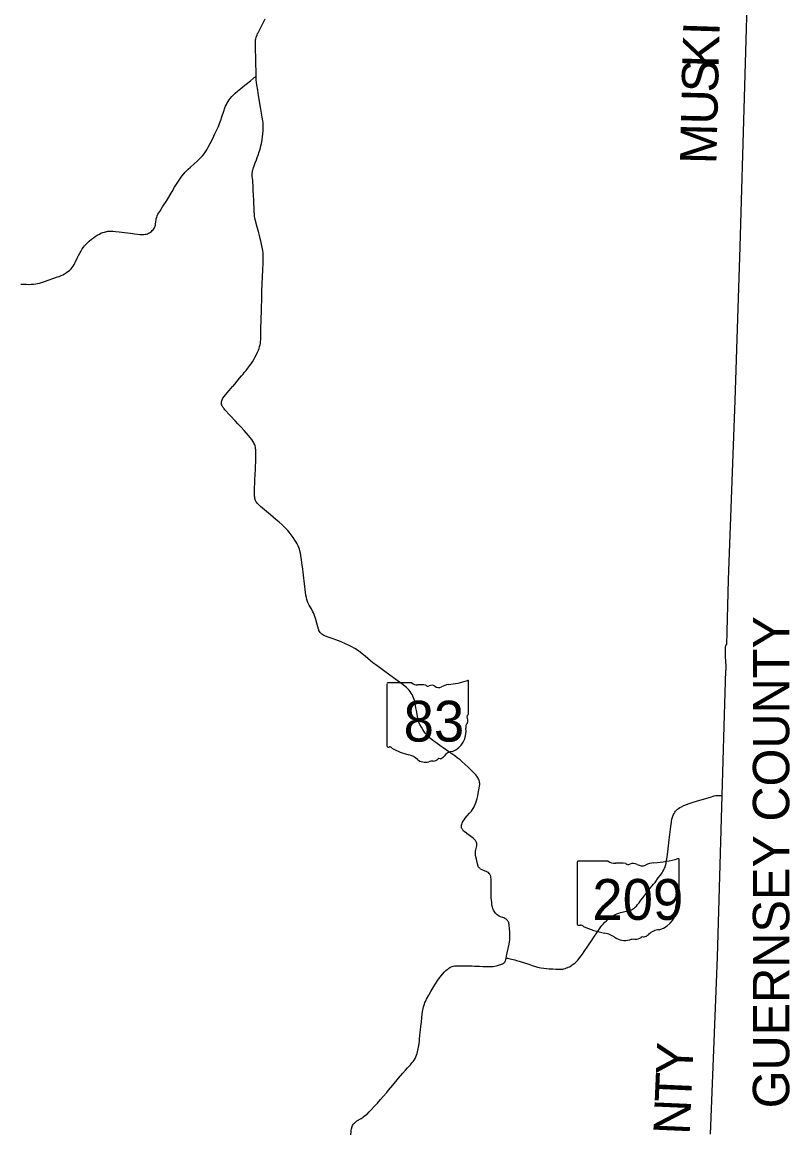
# Model space of a CAD drawing. Extents: x 2015843 to 2287843, y 623733 to 799733.
# Drawn here: x 2182200 to 2203288, y 737859 to 768366 of the extents above; entities that cross this region are included whole.
import ezdxf

# ---------------------------------------------------------------- set-up
doc = ezdxf.new("R2010")
doc.units = 0
for name, color, linetype in [('GM_X_County', 7, 'Continuous'), ('GM_X_County_Text', 7, 'Continuous'), ('GM_X_State_Location', 7, 'Continuous'), ('GM_X_State_Route', 7, 'Continuous'), ('GM_X_State_Shield', 7, 'Continuous')]:
    doc.layers.add(name, color=color, linetype=linetype)

msp = doc.modelspace()

# ---------------------------------------------------------------- linework, layer by layer
at = {"layer": 'GM_X_County'}
msp.add_lwpolyline([(2202153, 770412), (2201913, 762197), (2201774, 757977), (2201599, 753053), (2201548, 751275), (2201535, 751259), (2201527, 751247), (2201523, 751239), (2201518, 751226), (2201514, 751209), (2201511, 751194), (2201509, 751176), (2201509, 751156), (2201510, 751119), (2201511, 751074), (2201513, 751019), (2201516, 750940), (2201524, 750806), (2201531, 750688), (2201534, 750628), (2201532, 750592), (2201531, 750578), (2201529, 750569), (2201526, 750557), (2201479, 749033), (2201419, 747129), (2201296, 742683), (2201102, 737817)], dxfattribs=at)
at = {"layer": 'GM_X_State_Route'}
for points in [[(2188669, 768052), (2188682, 768076), (2188793, 768292), (2188847, 768408), (2188873, 768462)], [(2188609, 767690), (2188608, 767749), (2188609, 767831), (2188612, 767879), (2188617, 767911), (2188624, 767942), (2188627, 767954)], [(2188627, 767954), (2188634, 767973), (2188652, 768018), (2188669, 768052)], [(2188628, 766868), (2188628, 766930), (2188609, 767690)], [(2182163, 761171), (2182313, 761166), (2182379, 761165), (2182444, 761167), (2182510, 761171), (2182575, 761179), (2182623, 761187), (2182671, 761198), (2182734, 761215), (2182811, 761241), (2183166, 761368), (2183212, 761385), (2183273, 761410), (2183317, 761430), (2183360, 761454), (2183416, 761488), (2183457, 761515), (2183495, 761545), (2183519, 761567), (2183541, 761591), (2183572, 761628), (2183600, 761668), (2183625, 761710), (2183645, 761750), (2183655, 761769), (2183709, 761886), (2183748, 761960), (2183779, 762018), (2183819, 762088), (2183852, 762143), (2183882, 762185), (2183911, 762224), (2183945, 762263), (2183990, 762310), (2184039, 762355), (2184102, 762405), (2184156, 762446), (2184207, 762480), (2184262, 762515), (2184320, 762546), (2184364, 762567), (2184411, 762586), (2184457, 762603), (2184489, 762612), (2184521, 762619), (2184555, 762624), (2184591, 762626), (2184636, 762627), (2184692, 762625), (2184767, 762619), (2184865, 762607), (2185010, 762590), (2185092, 762580), (2185173, 762568), (2185286, 762552), (2185366, 762542), (2185431, 762535), (2185480, 762533), (2185513, 762533), (2185545, 762535), (2185577, 762540), (2185608, 762547), (2185639, 762557), (2185669, 762569), (2185697, 762584), (2185725, 762601), (2185750, 762620), (2185775, 762642), (2185795, 762663), (2185816, 762690), (2185833, 762718), (2185846, 762744), (2185853, 762762), (2185861, 762793), (2185866, 762824), (2185872, 762886), (2185880, 762937), (2185885, 762969), (2185897, 763012), (2185911, 763048), (2185930, 763089), (2185951, 763126), (2185978, 763171), (2186056, 763292), (2186169, 763471), (2186320, 763720), (2186387, 763833), (2186455, 763945), (2186508, 764029), (2186545, 764083), (2186585, 764135), (2186638, 764198), (2186681, 764245), (2186704, 764271), (2186762, 764330), (2186822, 764387), (2186920, 764474), (2187006, 764549), (2187066, 764605), (2187112, 764652), (2187156, 764700), (2187197, 764751), (2187235, 764804), (2187270, 764859), (2187311, 764930), (2187365, 765032), (2187416, 765134), (2187465, 765238), (2187493, 765297), (2187558, 765430), (2187591, 765505), (2187622, 765580), (2187656, 765673), (2187688, 765766), (2187738, 765922), (2187770, 766015), (2187789, 766061), (2187809, 766106), (2187832, 766150), (2187858, 766192), (2187886, 766233), (2187916, 766272), (2187958, 766323), (2188003, 766370), (2188051, 766416), (2188113, 766469), (2188203, 766542), (2188318, 766635), (2188470, 766759), (2188558, 766833), (2188576, 766846), (2188591, 766856), (2188607, 766862), (2188628, 766868)], [(2188533, 763998), (2188532, 764015), (2188526, 764080), (2188522, 764118), (2188519, 764175), (2188520, 764215), (2188524, 764258), (2188530, 764290), (2188542, 764331), (2188555, 764371), (2188573, 764421), (2188604, 764505), (2188634, 764585), (2188659, 764649), (2188681, 764710), (2188714, 764808), (2188735, 764881), (2188759, 764972), (2188774, 765036), (2188792, 765133), (2188794, 765142), (2188805, 765214), (2188814, 765296), (2188820, 765378), (2188821, 765460), (2188820, 765542), (2188817, 765592), (2188810, 765657), (2188797, 765755), (2188751, 766030), (2188696, 766353), (2188671, 766499), (2188647, 766644), (2188637, 766710), (2188631, 766782), (2188629, 766837), (2188628, 766868)], [(2190345, 751684), (2190342, 751691), (2190323, 751754), (2190266, 751959), (2190242, 752038), (2190220, 752100), (2190201, 752146), (2190180, 752191), (2190149, 752249), (2190087, 752356), (2190068, 752390), (2190051, 752423), (2190037, 752457), (2190020, 752511), (2190009, 752559), (2189996, 752623), (2189984, 752704), (2189898, 753412), (2189896, 753437), (2189894, 753453), (2189874, 753600), (2189856, 753713), (2189844, 753778), (2189828, 753842), (2189814, 753889), (2189797, 753936), (2189778, 753981), (2189750, 754041), (2189727, 754084), (2189693, 754141), (2189647, 754209), (2189590, 754289), (2189539, 754354), (2189497, 754405), (2189452, 754453), (2189405, 754499), (2189345, 754555), (2189258, 754630), (2189170, 754704), (2189020, 754831), (2188857, 754969), (2188745, 755065), (2188697, 755109), (2188674, 755132), (2188653, 755157), (2188634, 755181), (2188620, 755202), (2188606, 755232), (2188599, 755256), (2188592, 755287), (2188587, 755319), (2188584, 755351), (2188584, 755398), (2188584, 755414), (2188586, 755482), (2188595, 755794), (2188605, 756089), (2188615, 756367), (2188620, 756574), (2188619, 756621), (2188613, 756663), (2188607, 756696), (2188598, 756728), (2188587, 756759), (2188568, 756805), (2188552, 756834), (2188535, 756862), (2188507, 756903), (2188467, 756955), (2188413, 757018), (2188294, 757153), (2188217, 757238), (2188127, 757334), (2188060, 757405), (2187905, 757575), (2187771, 757720), (2187750, 757744), (2187738, 757756), (2187729, 757769), (2187718, 757782), (2187709, 757795), (2187701, 757809), (2187693, 757823), (2187687, 757838), (2187682, 757852), (2187678, 757868), (2187675, 757884), (2187674, 757900), (2187674, 757916), (2187676, 757931), (2187678, 757947), (2187682, 757963), (2187692, 757993), (2187707, 758022), (2187724, 758050), (2187743, 758076), (2187795, 758139), (2187880, 758239), (2187944, 758313), (2187972, 758346), (2187987, 758364), (2188039, 758426), (2188174, 758589), (2188226, 758652), (2188267, 758702), (2188298, 758740), (2188351, 758803), (2188403, 758867), (2188453, 758932), (2188491, 758985), (2188526, 759040), (2188560, 759097), (2188592, 759154), (2188637, 759242), (2188665, 759301), (2188691, 759361), (2188708, 759407), (2188723, 759454), (2188734, 759503), (2188743, 759551), (2188749, 759600), (2188752, 759649), (2188758, 759830), (2188760, 759944), (2188766, 760190), (2188772, 760453), (2188776, 760584), (2188779, 760698), (2188780, 760764), (2188787, 760977), (2188805, 761370), (2188814, 761567), (2188820, 761747), (2188822, 761862), (2188821, 761944), (2188816, 762026), (2188809, 762092), (2188801, 762141), (2188786, 762221), (2188764, 762318), (2188718, 762509), (2188689, 762620), (2188657, 762737), (2188603, 762943), (2188593, 762992), (2188586, 763030), (2188580, 763070), (2188579, 763109), (2188576, 763142), (2188573, 763217), (2188562, 763429), (2188553, 763655), (2188550, 763720), (2188545, 763834), (2188541, 763900), (2188538, 763949), (2188533, 763998)], [(2195494, 742655), (2195504, 742708), (2195523, 742805), (2195576, 743045), (2195588, 743109), (2195594, 743158), (2195598, 743208), (2195598, 743257), (2195593, 743372), (2195589, 743470), (2195582, 743559), (2195579, 743585), (2195573, 743610), (2195566, 743632), (2195561, 743647), (2195553, 743663), (2195545, 743677), (2195534, 743693), (2195519, 743709), (2195496, 743727), (2195480, 743736), (2195457, 743749), (2195432, 743761), (2195406, 743771), (2195345, 743795), (2195300, 743814), (2195272, 743830), (2195246, 743848), (2195222, 743870), (2195201, 743894), (2195182, 743920), (2195165, 743948), (2195151, 743978), (2195133, 744023), (2195123, 744054), (2195115, 744085), (2195105, 744133), (2195099, 744182), (2195092, 744247), (2195087, 744312), (2195084, 744406), (2195083, 744427), (2195084, 744560), (2195082, 744744), (2195082, 744799), (2195081, 744834), (2195076, 744872), (2195071, 744908), (2195066, 744923), (2195060, 744942), (2195051, 744959), (2195040, 744973), (2195031, 744985), (2195008, 745006), (2194984, 745023), (2194951, 745037), (2194923, 745047), (2194851, 745074), (2194822, 745088), (2194794, 745104), (2194782, 745114), (2194769, 745124), (2194758, 745135), (2194748, 745147), (2194739, 745160), (2194731, 745174), (2194724, 745189), (2194719, 745204), (2194714, 745219), (2194701, 745283), (2194679, 745378), (2194658, 745474), (2194653, 745505), (2194651, 745537), (2194651, 745570), (2194655, 745602), (2194660, 745634), (2194687, 745738), (2194690, 745761), (2194690, 745778), (2194690, 745795), (2194687, 745811), (2194685, 745826), (2194679, 745842), (2194674, 745854), (2194666, 745871), (2194656, 745887), (2194644, 745901), (2194619, 745926), (2194594, 745948), (2194529, 745998), (2194450, 746056), (2194370, 746114), (2194328, 746149), (2194302, 746177), (2194293, 746190), (2194283, 746207), (2194277, 746222), (2194272, 746237), (2194269, 746252), (2194267, 746268), (2194267, 746284), (2194269, 746299), (2194272, 746315), (2194276, 746331), (2194286, 746361), (2194300, 746390), (2194315, 746419), (2194341, 746460), (2194370, 746499), (2194422, 746562), (2194487, 746635), (2194541, 746697), (2194571, 746736), (2194589, 746763), (2194615, 746812), (2194638, 746856), (2194662, 746919), (2194679, 746975), (2194696, 747038), (2194715, 747118), (2194739, 747231), (2194757, 747327), (2194766, 747382), (2194770, 747425), (2194770, 747457), (2194767, 747480), (2194763, 747503), (2194762, 747510), (2194752, 747543), (2194740, 747571), (2194726, 747603), (2194710, 747631), (2194692, 747657), (2194665, 747688), (2194632, 747724), (2194566, 747790), (2194459, 747893), (2194363, 747982), (2194277, 748058), (2194228, 748101), (2194151, 748163), (2194085, 748212), (2193924, 748325), (2193762, 748438), (2193709, 748475), (2193562, 748580), (2193483, 748637), (2193431, 748678), (2193394, 748710), (2193362, 748740), (2193324, 748778), (2193292, 748815), (2193275, 748839), (2193232, 748896), (2193204, 748938), (2193168, 748997), (2193125, 749076), (2193117, 749096), (2193098, 749141), (2193081, 749192), (2193069, 749243), (2193057, 749304), (2193031, 749455), (2193018, 749536), (2192998, 749649), (2192989, 749689), (2192984, 749713), (2192971, 749761), (2192954, 749808), (2192935, 749853), (2192912, 749897), (2192886, 749939), (2192858, 749980), (2192827, 750019), (2192794, 750056), (2192758, 750090), (2192721, 750123), (2192669, 750163), (2192564, 750242), (2192298, 750434), (2192125, 750559), (2192019, 750636), (2191914, 750714), (2191834, 750772), (2191769, 750822), (2191693, 750889), (2191625, 750949), (2191544, 751017), (2191485, 751061), (2191414, 751113), (2191337, 751161), (2191242, 751215), (2191169, 751250), (2191079, 751291), (2190959, 751343), (2190821, 751397), (2190714, 751437), (2190574, 751486), (2190513, 751509), (2190484, 751523), (2190456, 751539), (2190431, 751559), (2190408, 751581), (2190387, 751606), (2190369, 751633), (2190354, 751661), (2190345, 751684)], [(2195494, 742655), (2195504, 742655), (2195519, 742654), (2195538, 742653), (2195574, 742646), (2195643, 742632), (2195730, 742607), (2195778, 742595), (2195857, 742572), (2196115, 742487), (2196212, 742455), (2196306, 742425), (2196358, 742412), (2196403, 742401), (2196452, 742393), (2196533, 742383), (2196673, 742366), (2196778, 742359), (2196864, 742355), (2196934, 742352), (2196991, 742352), (2197032, 742356), (2197050, 742357), (2197080, 742363), (2197116, 742373), (2197153, 742386), (2197193, 742402), (2197203, 742407), (2197234, 742421), (2197281, 742450), (2197311, 742471), (2197354, 742501), (2197388, 742529), (2197428, 742565), (2197462, 742601), (2197500, 742643), (2197552, 742707), (2197595, 742768), (2197643, 742835), (2197743, 742985), (2197861, 743162), (2197907, 743231), (2198004, 743382), (2198058, 743464), (2198096, 743518), (2198126, 743557), (2198158, 743594), (2198204, 743642), (2198252, 743686), (2198302, 743729), (2198368, 743779), (2198409, 743807), (2198451, 743832), (2198495, 743855), (2198540, 743875), (2198587, 743893), (2198634, 743908), (2198682, 743920), (2198755, 743935), (2198816, 743949), (2198865, 743962), (2198899, 743972), (2198936, 743986), (2198968, 744005), (2198996, 744023), (2199023, 744042), (2199048, 744063), (2199074, 744089), (2199108, 744126), (2199146, 744173), (2199198, 744247), (2199249, 744311), (2199306, 744388), (2199367, 744466), (2199454, 744577), (2199498, 744631), (2199547, 744687), (2199589, 744738), (2199676, 744859), (2199735, 744936), (2199782, 745002), (2199803, 745037), (2199827, 745080), (2199847, 745124), (2199860, 745157), (2199874, 745202), (2199888, 745264), (2199905, 745342), (2199920, 745426), (2199931, 745514), (2199940, 745578), (2199977, 745911), (2200002, 746125), (2200023, 746274), (2200036, 746388), (2200040, 746420), (2200049, 746468), (2200050, 746474), (2200057, 746501), (2200066, 746532), (2200076, 746561), (2200095, 746603), (2200109, 746632), (2200130, 746666), (2200152, 746696), (2200176, 746723), (2200183, 746730), (2200200, 746747), (2200232, 746771), (2200267, 746793), (2200311, 746817), (2200378, 746848), (2200452, 746878), (2200528, 746905), (2200607, 746931), (2200754, 746977), (2201109, 747082), (2201215, 747113), (2201253, 747122), (2201284, 747126), (2201325, 747129), (2201361, 747129), (2201404, 747128), (2201420, 747126)], [(2193182, 741027), (2193202, 741190), (2193214, 741270), (2193223, 741318), (2193232, 741350), (2193248, 741396), (2193266, 741441), (2193280, 741470), (2193309, 741529), (2193370, 741644), (2193427, 741744), (2193539, 741925), (2193619, 742049), (2193666, 742116), (2193706, 742168), (2193748, 742218), (2193803, 742278), (2193838, 742313), (2193874, 742346), (2193899, 742366), (2193925, 742385), (2193953, 742401), (2193982, 742415), (2194012, 742427), (2194043, 742436), (2194075, 742442), (2194107, 742446), (2194139, 742448), (2194171, 742449), (2194236, 742448), (2194417, 742445), (2194449, 742444), (2194564, 742442), (2194629, 742440), (2194712, 742437), (2194760, 742435), (2194858, 742431), (2195038, 742425), (2195071, 742424), (2195104, 742425), (2195137, 742428), (2195186, 742436), (2195217, 742445), (2195256, 742455), (2195282, 742462), (2195364, 742490), (2195393, 742503), (2195423, 742517), (2195439, 742526), (2195452, 742539), (2195455, 742543), (2195462, 742552), (2195470, 742565), (2195476, 742580), (2195482, 742596), (2195486, 742611), (2195494, 742655)], [(2191229, 737803), (2191235, 737885), (2191240, 737934), (2191246, 737967), (2191253, 737999), (2191258, 738015), (2191262, 738026), (2191266, 738035), (2191278, 738060), (2191295, 738089), (2191305, 738102), (2191316, 738115), (2191328, 738127), (2191334, 738133), (2191356, 738153), (2191394, 738184), (2191445, 738214), (2191462, 738225), (2191515, 738255), (2191563, 738286), (2191597, 738313), (2191636, 738343), (2191674, 738375), (2191734, 738431), (2191791, 738490), (2191880, 738587), (2191957, 738672), (2192043, 738770), (2192119, 738857), (2192214, 738969), (2192267, 739032), (2192381, 739172), (2192541, 739359), (2192659, 739495), (2192735, 739581), (2192790, 739642), (2192866, 739727), (2192909, 739777), (2192939, 739816), (2192968, 739857), (2192993, 739899), (2193016, 739943), (2193035, 739989), (2193051, 740036), (2193063, 740084), (2193080, 740164), (2193096, 740261), (2193111, 740375), (2193117, 740424), (2193128, 740538), (2193144, 740685), (2193154, 740782), (2193168, 740896), (2193182, 741027)]]:
    msp.add_lwpolyline(points, dxfattribs=at)
at = {"layer": 'GM_X_State_Shield'}
for p, q in [((2192222, 750187), (2192222, 748486)), ((2192901, 750216), (2192244, 750216)), ((2194464, 749369), (2194464, 750258)), ((2194463, 749369), (2194464, 749369)), ((2197451, 745290), (2197451, 743589)), ((2198299, 745320), (2197478, 745320)), ((2200252, 744472), (2200252, 745362)), ((2200252, 744472), (2200252, 744472))]:
    msp.add_line(p, q, dxfattribs=at)
for centre, radius, start, end in [((2192248, 750191), 26, 98.1301, 188.1301), ((2193057, 750414), 252, 231.6195, 271.1119), ((2193968, 749697), 478, 97.3462, 120.7689), ((2193665, 752536), 2377, 275.8445, 288.9065), ((2194439, 750262), 25, 351.8621, 97.738), ((2193141, 749261), 904, 80.4867, 94.9883), ((2193346, 750199), 72.7, 219.7921, 297.1024), ((2193452, 750003), 151, 54.4667, 119.1411), ((2193647, 750273), 182, 233.8562, 294.8282), ((2194458, 749303), 38.6, 107.944, 210.337), ((2194212, 749191), 232, 340.033, 23.6496), ((2194437, 749365), 26.7, 289.6038, 7.7341), ((2193798, 748883), 595, 292.3089, 8.9858), ((2194553, 748996), 169, 136.8065, 186.9296), ((2192248, 748482), 26.2, 171.9584, 258.3066), ((2192252, 748656), 200, 267.339, 280.6039), ((2192293, 748388), 72.1, 29.7484, 93.2717), ((2193203, 749916), 1716, 240.4129, 257.1985), ((2192691, 747722), 537, 47.1842, 75.836), ((2193272, 748379), 341, 230.7004, 286.2918), ((2193469, 747791), 280, 85.6951, 111.2099), ((2193494, 748252), 182, 268.777, 315.5493), ((2193658, 748087), 51.1, 65.7517, 132.6484), ((2193637, 748321), 192, 282.8732, 323.2771), ((2194049, 748008), 326, 94.4031, 142.5768)]:
    msp.add_arc(centre, radius, start, end, dxfattribs=at)
for centre, major_axis, start_param, end_param in [((2197483, 745294), (32.5, 0), 1.712693, 3.28349), ((2198494, 745517), (315, 0), 4.042523, 4.731795), ((2199254, 747639), (2971, 0), 4.814394, 5.042369), ((2200221, 745365), (31.2, 0), 6.141152, 7.989035), ((2198598, 744365), (1130, 0), 1.404758, 1.657858), ((2198855, 745303), (90.8, 0), 3.836095, 5.185415), ((2198988, 745106), (189, 0), 0.950623, 2.079405), ((2199232, 745376), (227, 0), 4.081561, 5.145723), ((2199633, 744800), (598, 0), 1.699011, 2.107814), ((2200245, 744407), (48.3, 0), 1.883978, 3.671073), ((2199938, 744294), (290, 0), 5.934695, 6.695948), ((2200219, 744468), (33.4, 0), 5.05454, 6.418171), ((2199421, 743986), (743, 0), 5.101752, 6.440018), ((2200364, 744099), (211, 0), 2.387724, 3.262537), ((2197483, 743585), (32.7, 0), 3.00124, 4.508301), ((2197488, 743759), (250, 0), 4.665946, 4.897461), ((2197539, 743491), (90.1, 0), 0.519207, 1.627899), ((2198677, 745019), (2146, 0), 4.195997, 4.488961), ((2198037, 742825), (671, 0), 0.823519, 1.323587), ((2198763, 743483), (426, 0), 4.026481, 4.996735), ((2199009, 742894), (350, 0), 1.495662, 1.94098), ((2199040, 743355), (227, 0), 4.691044, 5.507374), ((2199246, 743190), (63.9, 0), 1.147584, 2.315152), ((2199218, 743424), (240, 0), 4.937069, 5.64225), ((2199734, 743112), (407, 0), 1.647645, 2.488434)]:
    msp.add_ellipse(centre, major_axis=major_axis, ratio=0.8, start_param=start_param, end_param=end_param, dxfattribs=at)

# ---------------------------------------------------------------- texts
at = {"layer": 'GM_X_County_Text'}
for s, rotation, p in [('I', 88.1853, (2201353, 767990)), ('K', 88.5993, (2201332, 767108)), ('S', 88.6929, (2201316, 766431)), ('U', 88.6907, (2201296, 765547)), ('M', 88.692, (2201271, 764460)), ('GUERNSEY COUNTY', 90, (2203274, 738531)), ('Y', 87.501, (2200607, 739425)), ('T', 87.4973, (2200575, 738677)), ('N', 87.5004, (2200536, 737794))]:
    msp.add_text(s, height=1000, rotation=rotation, dxfattribs=at).set_placement(p)
at = {"layer": 'GM_X_State_Location'}
for s, p in [('s', (2182927, 761207)), ('r', (2182927, 761207)), ('s', (2193130, 748852)), ('r', (2193130, 748852)), ('s', (2199044, 743941)), ('r', (2199044, 743941))]:
    msp.add_text(s, height=1, dxfattribs=at).set_placement(p)
for s, p in [('93', (2182675, 761134)), ('83', (2192878, 748779)), ('209', (2198691, 743868))]:
    msp.add_text(s, height=1, rotation=0, dxfattribs=at).set_placement(p)
at = {"layer": 'GM_X_State_Shield'}
for s, p in [('83', (2192678, 748606)), ('209', (2197863, 743709))]:
    msp.add_text(s, height=1120.7, dxfattribs=at).set_placement(p)

doc.saveas('drawing.dxf')
